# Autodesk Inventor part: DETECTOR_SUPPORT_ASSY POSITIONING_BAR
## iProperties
Shininess: 64.0
Length Units: 11272
Angle Units: 11279
Time Units: 11290
Mass Units: 11286
Length Display Precision: 3
Angle Display Precision: 2
Compacted: True
Part Number: DETECTOR_SUPPORT_ASSY POSITIONING_BAR
Document SubType Name: Modeling
Created: 2004-08
Designer: John Blackburn
Material: ALUMINUM
Manufacturer: Standard
Standards Organization: Custom
Density: 0.0
Volumn: 0.0
Area: 0.0
PropertySet Name: Model Information
Control State: 0
Master: False
Checked Out: False
Author: John Blackburn
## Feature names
1. ExtrusionMidplane1
2. AM_HOLE_0301DE_1 [Hole]
3. AM_HOLE_0301DE_2 [Hole]
